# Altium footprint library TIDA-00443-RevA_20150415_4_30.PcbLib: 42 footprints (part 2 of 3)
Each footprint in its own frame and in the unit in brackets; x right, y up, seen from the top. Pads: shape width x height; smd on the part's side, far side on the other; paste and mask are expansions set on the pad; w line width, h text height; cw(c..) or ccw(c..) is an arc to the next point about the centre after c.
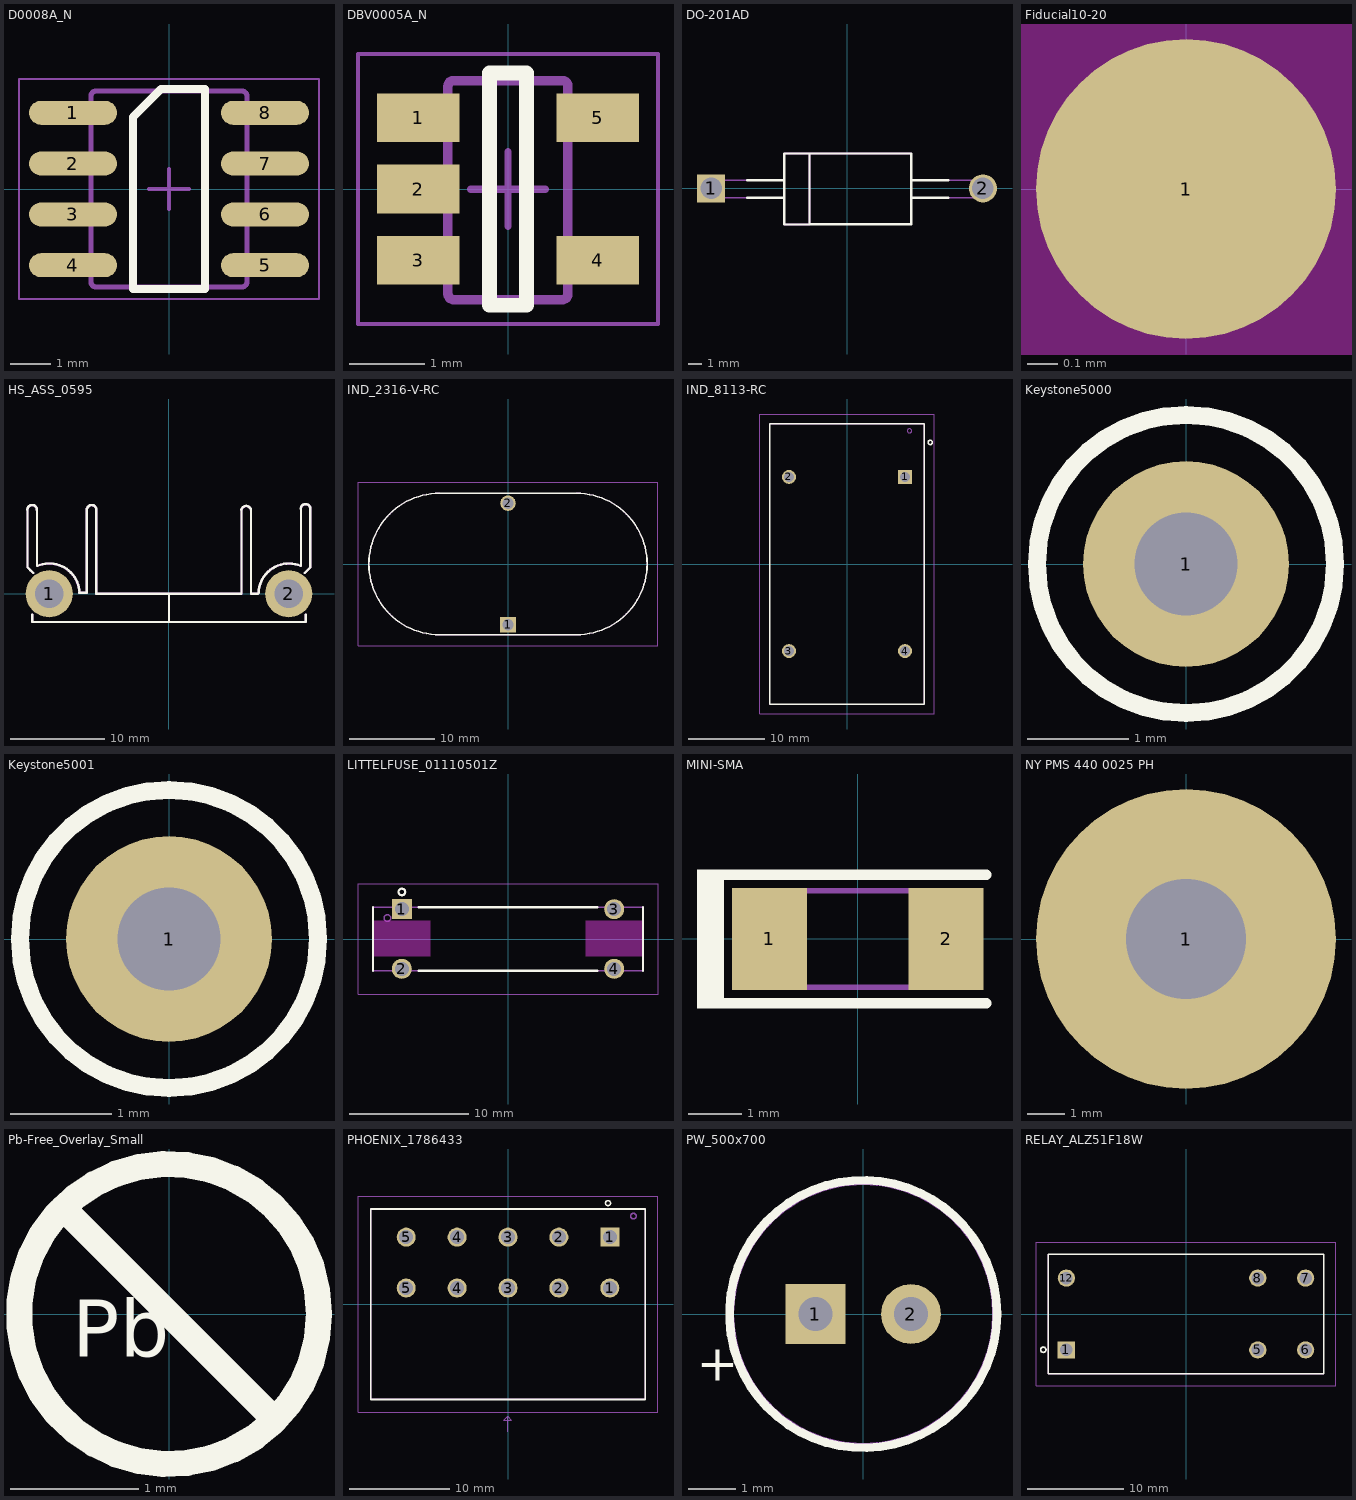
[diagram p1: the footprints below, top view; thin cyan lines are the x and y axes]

## D0008A_N [mm] "SOIC, 8-Leads, Body 4.9x3.9mm, Pitch 1.27mm, IPC Medium Density"
height 1.75
pads (8):
  oval 2.2x0.6 smd: 1(-2.4,1.905) 2(-2.4,0.635) 3(-2.4,-0.635) 4(-2.4,-1.905) 5(2.4,-1.905) 6(2.4,-0.635) 7(2.4,0.635) 8(2.4,1.905)
Top Overlay:
  lines w0.2: -0.9,-2.5 -0.9,1.8 -0.2,2.5 0.9,2.5 0.9,-2.5 -0.9,-2.5
Mechanical 5:
  lines w0.127: -2.375,-2.095 -1.995,-2.095 -1.952,-2.095 -1.952,-1.715 -1.995,-1.715 -2.375,-1.715 ; -2.375,-2.095 -2.589,-2.095 -3.002,-2.095 -3.002,-1.715 -2.589,-1.715 -2.375,-1.715 ; -2.375,-2.095 -2.375,-1.715 ; -2.375,-0.825 -1.995,-0.825 -1.952,-0.825 -1.952,-0.445 -1.995,-0.445 -2.375,-0.445 ; -2.375,-0.825 -2.589,-0.825 -3.002,-0.825 -3.002,-0.445 -2.589,-0.445 -2.375,-0.445 ; -2.375,-0.825 -2.375,-0.445 ; -2.375,0.445 -1.995,0.445 -1.952,0.445 -1.952,0.825 -1.995,0.825 -2.375,0.825 ; -2.375,0.445 -2.589,0.445 -3.002,0.445 -3.002,0.825 -2.589,0.825 -2.375,0.825 ; -2.375,0.445 -2.375,0.825 ; -2.375,1.715 -1.995,1.715 -1.952,1.715 -1.952,2.095 -1.995,2.095 -2.375,2.095 ; -2.375,1.715 -2.589,1.715 -3.002,1.715 -3.002,2.095 -2.589,2.095 -2.375,2.095 ; -2.375,1.715 -2.375,2.095 ; -0.332,-2.45 -1.825,-2.45 -1.826,-2.45 cw(c-1.825,-2.323) -1.952,-2.324 -1.952,-2.323 -1.952,2.323 -1.952,2.324 cw(c-1.825,2.323) -1.826,2.45 -1.825,2.45 -0.332,2.45 ; -0.332,-2.45 -0.182,-2.45 ; -0.332,-2.45 -0.182,-2.45 ; -0.332,2.45 -0.182,2.45 ; -0.332,2.45 -0.182,2.45 ; -0.182,-2.45 0.178,-2.45 ; -0.182,2.45 0.178,2.45 ; 0.178,-2.45 0.328,-2.45 ; 0.178,-2.45 0.328,-2.45 ; 0.178,2.45 0.328,2.45 ; 0.178,2.45 0.328,2.45 ; 0.328,-2.45 1.821,-2.45 1.822,-2.45 ccw(c1.821,-2.323) 1.948,-2.324 1.948,-2.323 1.948,2.323 1.948,2.324 ccw(c1.821,2.323) 1.822,2.45 1.821,2.45 0.328,2.45 ; 2.371,-2.095 2.585,-2.095 2.998,-2.095 2.998,-1.715 2.585,-1.715 2.371,-1.715 ; 2.371,-2.095 1.991,-2.095 1.948,-2.095 1.948,-1.715 1.991,-1.715 2.371,-1.715 ; 2.371,-2.095 2.371,-1.715 ; 2.371,-0.825 2.585,-0.825 2.998,-0.825 2.998,-0.445 2.585,-0.445 2.371,-0.445 ; 2.371,-0.825 1.991,-0.825 1.948,-0.825 1.948,-0.445 1.991,-0.445 2.371,-0.445 ; 2.371,-0.825 2.371,-0.445 ; 2.371,0.445 2.585,0.445 2.998,0.445 2.998,0.825 2.585,0.825 2.371,0.825 ; 2.371,0.445 1.991,0.445 1.948,0.445 1.948,0.825 1.991,0.825 2.371,0.825 ; 2.371,0.445 2.371,0.825 ; 2.371,1.715 2.585,1.715 2.998,1.715 2.998,2.095 2.585,2.095 2.371,2.095 ; 2.371,1.715 1.991,1.715 1.948,1.715 1.948,2.095 1.991,2.095 2.371,2.095 ; 2.371,1.715 2.371,2.095
  text ".Designator" at 0.698,0.241 h0.76
Mechanical 15:
  lines w0.05: -3.75,-2.75 -3.75,2.75 3.75,2.75 3.75,-2.75 -3.75,-2.75
  lines w0.1: -0.5,0 0.5,0 ; 0,-0.5 0,0.5
3D body: height 1.63, standoff 0, extent -3,-2.45 3,2.45

## DBV0005A_N [mm] "SOT23, 5-Leads, Body 2.9x1.6mm, Pitch 0.95mm, Lead Span 2.8mm, IPC Medium Density"
height 1.45
pads (5):
  rect 1.1x0.65 smd: 1(-1.2,0.95) 2(-1.2,0) 3(-1.2,-0.95) 4(1.2,-0.95) 5(1.2,0.95)
Top Overlay:
  lines w0.2: -0.25,-1.55 0.25,-1.55 0.25,1.55 -0.25,1.55 -0.25,-1.55
Mechanical 5:
  lines w0.127: -0.801,1.371 cw(c-0.725,1.37) -0.725,1.446 ; -0.801,1.37 -0.801,-1.399 -0.801,-1.4 ccw(c-0.725,-1.399) -0.725,-1.475 ; -0.801,1.37 -0.801,1.371 ; -0.725,-1.475 -0.725,-1.475 ; -0.725,-1.475 0.723,-1.475 0.724,-1.475 ccw(c0.723,-1.399) 0.799,-1.4 0.799,-1.399 0.799,1.37 ; -0.725,1.446 0.723,1.446 0.724,1.446 cw(c0.723,1.37) 0.799,1.371 ; -0.725,1.446 -0.725,1.446 ; 0.799,1.37 0.799,1.371 ; -1.423,-1.167 -1.199,-1.167 -1.105,-1.167 -1.088,-1.167 -0.835,-1.167 -0.801,-1.167 -0.801,-0.767 -0.835,-0.767 -1.088,-0.767 -1.105,-0.767 -1.199,-0.767 -1.423,-0.767 -1.423,-1.167 ; -1.423,-0.215 -1.199,-0.215 -1.105,-0.215 -1.088,-0.215 -0.835,-0.215 -0.801,-0.215 -0.801,0.186 -0.835,0.186 -1.088,0.186 -1.105,0.186 -1.199,0.186 -1.423,0.186 -1.423,-0.215 ; -1.423,0.738 -1.199,0.738 -1.105,0.738 -1.088,0.738 -0.835,0.738 -0.801,0.738 -0.801,1.138 -0.835,1.138 -1.088,1.138 -1.105,1.138 -1.199,1.138 -1.423,1.138 -1.423,0.738 ; 0.799,-1.167 0.799,-0.767 0.834,-0.767 1.087,-0.767 1.103,-0.767 1.198,-0.767 1.422,-0.767 1.422,-1.167 1.198,-1.167 1.103,-1.167 1.087,-1.167 0.834,-1.167 0.799,-1.167 ; 0.799,0.738 0.799,1.138 0.834,1.138 1.087,1.138 1.103,1.138 1.198,1.138 1.422,1.138 1.422,0.738 1.198,0.738 1.103,0.738 1.087,0.738 0.834,0.738 0.799,0.738
  text ".Designator" at 0.349,-0.645 h0.76
Mechanical 15:
  lines w0.05: -2,-1.8 -2,1.8 2,1.8 2,-1.8 -2,-1.8
  lines w0.1: -0.5,0 0.5,0 ; 0,-0.5 0,0.5
3D body: height 1.08, standoff -0.01, extent -1.422,-1.461 1.422,1.46

## DO-201AD [mm] "Vishay dimensions"
height 5.5
pads (2):
  rect 2.1x2.1 hole 1.6: 1(-10.16,0)
  round 2.1 hole 1.6: 2(10.16,0)
Top Overlay:
  lines w0.178: -7.47,-0.7 -4.7,-0.7 ; -7.47,0.62 -4.7,0.62 ; -2.8,-2.69 4.8,-2.69 4.8,2.61 -2.8,2.61 ; 4.8,-0.7 7.57,-0.7 ; 4.8,0.62 7.57,0.62 ; -2.8,2.61 -2.8,-2.7 -4.7,-2.7 -4.7,2.61 -2.8,2.61
Mechanical 5:
  lines w0.127: -4.7,-0.7 -7.47,-0.7 -10.11,-0.7 cw(c-10.11,-0.04) -10.11,0.62 -7.47,0.62 -4.7,0.62 ; -2.8,-2.69 4.8,-2.69 4.8,2.61 -2.8,2.61 ; 4.8,-0.7 7.57,-0.7 10.21,-0.7 ccw(c10.21,-0.04) 10.21,0.62 7.57,0.62 4.8,0.62 ; -2.8,2.61 -4.7,2.61 -4.7,-2.7 -2.8,-2.7 -2.8,2.61
  text ".Designator" at 0.787,0.203 h0.76
3D body: height 5.33, standoff -2.54, extent -10.819,-2.741 10.819,2.609

## Fiducial10-20 [mm]
pads (1):
  round 1 smd mask+0.5: 1(0,0)
Top Layer keep-out:
  circle w1.178: c0,0 r0.5

## HS_ASS_0595 [mm]
height 50
pads (2):
  round 5 hole 3: 1(-12.7,0) 2(12.7,0)
Top Overlay:
  lines w0.25: -15,9 -15,2.8 -14.697,2.497 -14.4,2.2 ; -14.5,-2.2 -14.5,-3 14.5,-3 14.5,-2.2 ; -14,3 -14,9 ; -9.5,0.1 -8.7,0.1 -8.7,9 ; -7.7,9 -7.7,0 0,0 ; 0,-3 0,0 ; 7.7,9 7.7,0 0,0 ; 8.7,9 8.7,0 9.413,0 ; 14,3 14,9 ; 14.4,2.2 14.712,2.512 15,2.8 15,2.9 15,9
  lines w0.254: -15.02,8.9 cw(c-14.51,8.9) -14,8.9 ; -13.974,2.942 cw(c-12.687,0.01) -9.487,0.1 ; -8.7,8.9 cw(c-8.19,8.9) -7.68,8.9 ; 7.68,8.9 cw(c8.19,8.79) 8.7,8.9 ; 9.512,0.1 cw(c12.713,0.01) 13.979,2.951 ; 13.98,9 cw(c14.49,9) 15,9
Mechanical 5:
  lines w0.25: -15,8.9 -15,2.8 -14.4,2.2 ; -14.5,-2.2 -14.5,-3 14.5,-3 14.5,-2.2 ; -14,3.1 -14,8.9 ; -8.7,9 -8.7,0.1 ; -7.7,8.9 -7.7,0 7.7,0 7.7,8.9 ; 0,-3 0,0 ; 8.7,8.9 8.7,0 9.4,0 ; 14,3 14,9 ; 14.4,2.2 15,2.8 ; 15,9 15,2.8 ; -14.4,2.2 -14.4,2.2 ; -8.7,0.1 -9.5,0.1 -8.7,0.1 ; 15,2.8 15,2.8
  lines w0.254: -15,8.9 cw(c-14.5,8.9) -14,8.9 ; -13.938,2.952 cw(c-12.7,0) -9.5,0.1 ; -8.7,8.9 cw(c-8.2,8.9) -7.7,8.9 ; 7.7,8.8 cw(c8.2,8.8) 8.7,8.8 ; 9.5,0.1 cw(c12.7,0) 13.973,2.938 ; 14,9 cw(c14.5,9) 15,9
  text ".Designator" at 1.016,0.787 h0.76
3D body: height 50, standoff 0, extent -15.1,-3.1 15.1,9.5
3D body: height 4.5, standoff 0, extent 10.22,-2.495 15.2,2.495
3D body: height 4.5, standoff 0, extent -15.18,-2.495 -10.2,2.495

## IND_2316-V-RC [mm] "INDUCTOR, TOROID, VERTICAL, 2PIN, TH"
height 32.512
pads (2):
  rect 1.82x1.82 / inner round 1.82 / far side rect 1.82x1.82 hole 1.32: 1(0,-7.112)
  round 1.82 hole 1.32: 2(0,7.112)
Top Overlay:
  lines w0.178: -8.001,-8.255 cw(c-8.001,0) -8.001,8.255 8.001,8.255 cw(c8.001,0) 8.001,-8.255 -8.001,-8.255
Bottom Overlay:
  lines w0.178: -15.775,-2.777 cw(c-8.001,0) -15.588,3.252 ; -13.59,6.076 cw(c-8.001,0) -8.001,8.255 ; -13.553,-6.109 ccw(c-8.001,0) -8.001,-8.255 ; -5.501,8.255 -2,8.255 ; -5.25,-8.255 -1.749,-8.255 ; 1.749,8.255 5.25,8.255 ; 2,-8.255 5.501,-8.255 ; 7.68,8.249 cw(c8.001,0) 14.473,5.124 ; 8.001,-8.255 ccw(c8.001,0) 14.986,-4.399 ; 15.575,3.283 cw(c8.001,0) 15.948,-2.235
Mechanical 5:
  lines w0.127: -8.001,-8.255 cw(c-8.001,0) -8.001,8.255 8.001,8.255 cw(c8.001,0) 8.001,-8.255 -8.001,-8.255
  text ".Designator" at -1.524,-0.508 h0.76
Mechanical 15:
  lines w0.05: -17.526,-9.525 -17.526,9.525 17.526,9.525 17.526,-9.525 -17.526,-9.525
3D body: height 32.51, standoff 0, extent -16.256,-8.255 16.256,8.255

## IND_8113-RC [mm] "INDUCTOR, CHOKE, COMMON MODE, 4 PIN, TH"
height 38.1
pads (4):
  rect 1.85x1.85 / inner round 1.85 / far side rect 1.85x1.85 hole 1.35 paste+0 mask+0.05: 1(7.62,11.43)
  round 1.85 hole 1.35 paste+0 mask+0.05: 2(-7.62,11.43) 3(-7.62,-11.43) 4(7.62,-11.43)
Top Overlay:
  circle w0.178: c10.922,15.951 r0.279
  lines w0.178: -10.16,-18.415 -10.16,18.415 10.16,18.415 10.16,-18.415 -10.16,-18.415
Bottom Overlay:
  lines w0.178: -10.16,-15.5 -10.16,-11 ; -10.16,-8.5 -10.16,-4.5 ; -10.16,-1.25 -10.16,3 ; -10.16,5.5 -10.16,10 ; -10.16,12.5 -10.16,16.5 ; -8.75,-18.415 -4.5,-18.415 ; -8.75,18.415 -4.5,18.415 ; -2,-18.415 2.5,-18.415 ; -2,18.415 2.5,18.415 ; 5,-18.415 9,-18.415 ; 5,18.415 9,18.415 ; 10.16,-15.25 10.16,-10.75 ; 10.16,-8.25 10.16,-4.25 ; 10.16,-1 10.16,3.25 ; 10.16,5.75 10.16,10.25 ; 10.16,12.75 10.16,16.75
Mechanical 5:
  circle w0.127: c8.204,17.475 r0.279
  lines w0.127: -10.16,-18.415 10.16,-18.415 10.16,18.415 -10.16,18.415 -10.16,-18.415
  text ".Designator" at 1.27,0.406 h0.76
Mechanical 15:
  lines w0.05: -11.43,-19.685 -11.43,19.685 11.43,19.685 11.43,-19.685 -11.43,-19.685
Mechanical 17:
  text "LEAD LENGTH: 5.08 MM" at -9.5,14.75 h1
3D body: height 38.1, standoff 0, extent -10.16,-18.415 10.16,18.415

## Keystone5000 [mil] "For Keystone 500x miniature loop terminals"
height 181.1
pads (1):
  round 80 hole 40: 1(0,0)
Top Overlay:
  circle w7: c0,0 r58
Mechanical 5:
  circle w5: c0,0 r58.31
  text ".Designator" at -42,-17 h30
3D body: height 181.97, standoff -118.11, extent -49,-49 49.04,49.24

## Keystone5001 [mil] "For Keystone 500x miniature loop terminals"
height 181.1
pads (1):
  round 80 hole 40: 1(0,0)
Top Overlay:
  circle w7: c0,0 r58
Mechanical 5:
  circle w5: c0,0 r58.31
  text ".Designator" at -40,-13 h30
3D body: height 181.97, standoff -118.11, extent -49,-49 49.04,49.24

## LITTELFUSE_01110501Z [mm] "FUSE CLIP, CARTRIDGE, 250V, 10A, PCB"
height 7.1
pads (4):
  rect 1.67x1.67 / inner round 1.67 / far side rect 1.67x1.67 hole 1.17: 1(-8.9,2.5)
  round 1.67 hole 1.17: 2(-8.9,-2.5) 3(8.9,2.5) 4(8.9,-2.5)
Top Layer keep-out:
  rectangle: -11.292,-1.468 -6.492,1.532
  rectangle: 6.508,-1.468 11.308,1.532
Top Overlay:
  circle w0.178: c-8.892,3.942 r0.279
  lines w0.178: -11.3,-2.66 -11.3,2.66 ; -7.5,-2.66 7.5,-2.66 ; -7.5,2.66 7.5,2.66 ; 11.3,-2.66 11.3,2.66
Bottom Overlay:
  lines w0.178: -11.3,-2.66 -11.3,-0.985 ; -11.3,0.985 -11.3,2.66 ; -7.5,-2.66 -5.825,-2.66 ; -7.5,2.66 -5.825,2.66 ; -4.15,-2.66 -2.475,-2.66 ; -4.15,2.66 -2.475,2.66 ; -0.8,-2.66 0.875,-2.66 ; -0.8,2.66 0.875,2.66 ; 2.55,-2.66 4.225,-2.66 ; 2.55,2.66 4.225,2.66 ; 5.825,2.66 7.5,2.66 ; 5.9,-2.66 7.575,-2.66 ; 11.3,-2.66 11.3,-0.985 ; 11.3,0.985 11.3,2.66
Mechanical 5:
  circle w0.127: c-10.109,1.753 r0.279
  lines w0.127: -11.3,-2.66 -11.3,2.66 11.3,2.66 11.3,-2.66 -11.3,-2.66
  text ".Designator" at -1.88,0.61 h0.76
Mechanical 15:
  lines w0.05: -12.57,-4.63 12.57,-4.63 12.57,4.63 -12.57,4.63 -12.57,-4.63
3D body: height 7.1, standoff 0, extent -11.3,-2.66 11.3,2.66

## MINI-SMA [mm] "COMCHIP"
height 1.45
pads (2):
  rect 1.4x1.9 smd: 1(-1.65,0) 2(1.65,0)
Top Overlay:
  rectangle: -2.999,-1.3 -2.499,1.3
  lines w0.2: -2.8,-1.2 2.4,-1.2 ; -2.8,1.2 2.4,1.2
Mechanical 5:
  rectangle: -2,-0.9 -1.3,0.9
  lines w0.1: -2,-0.9 -1.5,-0.9 0,-0.9 2,-0.9 2,0.9 -2,0.9 -2,-0.9
  text ".Designator" at -0.356,-0.279 h0.76
3D body: height 1.7, standoff 0, extent -1.95,-0.9 1.95,0.9

## NY PMS 440 0025 PH [mm] "4-40 nylon screw and mounting hole"
height 1.905
pads (1):
  round 8 hole 3.2: 1(0,0)
Mechanical 5:
  circle w0.127: c0,0 r3.789
  text ".Designator" at -1.524,-0.508 h1.02
3D body: height 2.69, standoff -8.74, extent -3.302,-3.3 3.296,3.3

## Pb-Free_Overlay_Small [mm]
Top Overlay:
  circle w0.203: c0,0 r1.168
  lines w0.203: -0.826,0.826 0.826,-0.826
  text "Pb" at -0.752,-0.48 h0.76

## PHOENIX_1786433 [mm] "TERM BLOCK, HDR, 5POS, R/A 5.08MM"
height 10.2
pads (10):
  round 1.9 hole 1.4: 1(10.16,1.61) 2(5.08,1.61) 2(5.08,6.69) 3(0,1.61) 3(0,6.69) 4(-5.08,1.61) 4(-5.08,6.69) 5(-10.16,1.61) 5(-10.16,6.69)
  rect 1.9x1.9 / inner round 1.9 / far side rect 1.9x1.9 hole 1.4: 1(10.16,6.69)
Top Overlay:
  circle w0.152: c9.982,10.084 r0.254
  lines w0.178: -13.7,-9.5 13.7,-9.5 13.7,9.5 -13.7,9.5 -13.7,-9.5
  text ".Designator" at 14.097,3.658 h0.76
Bottom Overlay:
  lines w0.178: -13.7,-9.5 -13.7,-8.475 ; -13.7,-7.1 -13.7,-5.5 ; -13.7,-4.1 -13.7,-2.5 ; -13.7,-1.1 -13.7,0.5 ; -13.7,1.9 -13.7,3.5 ; -13.7,4.9 -13.7,6.5 ; -13.7,7.9 -13.7,9.5 ; -11.913,9.5 -10.338,9.5 ; -10.846,-9.499 -9.271,-9.499 ; -8.913,9.5 -7.338,9.5 ; -7.846,-9.509 -6.271,-9.509 ; -5.913,9.5 -4.338,9.5 ; -4.846,-9.5 -3,-9.5 ; -2.413,9.5 -0.838,9.5 ; -1.168,-9.5 0.406,-9.5 ; 0.587,9.491 2.162,9.491 ; 1.832,-9.5 3.406,-9.5 ; 3.587,9.491 5.162,9.491 ; 4.832,-9.5 6.406,-9.5 ; 6.587,9.491 8.162,9.491 ; 7.832,-9.5 9.406,-9.5 ; 9.587,9.491 11.162,9.491 ; 10.832,-9.5 12.406,-9.5 ; 13.7,-9.5 13.7,-7.9 ; 13.701,-6.525 13.701,-4.925 ; 13.701,-3.525 13.701,-1.925 ; 13.701,-0.525 13.701,1.075 ; 13.701,2.475 13.701,4.075 ; 13.701,5.475 13.701,7.075 ; 13.701,8.475 13.701,9.5
Mechanical 5:
  circle w0.127: c12.522,8.788 r0.279
  lines w0.127: -13.7,-9.5 -13.7,9.5 13.7,9.5 13.7,-9.5 -13.7,-9.5
  text ".Designator" at -0.559,3.835 h0.76
Mechanical 15:
  lines w0.05: -14.97,-10.77 14.97,-10.77 14.97,10.77 -14.97,10.77 -14.97,-10.77
Mechanical 16:
  lines w0.05: -0.044,-12.732 -0.044,-11.208 ; -0.044,-11.208 0.337,-11.589 -0.425,-11.589 -0.044,-11.208
Mechanical 17:
  text "LEAD LENGTH: 3.50MM" at -9.487,-4.244 h1
  text "MATING SIDE" at -5.512,-14.138 h1
3D body: height 10.2, standoff 0, extent -13.716,-9.515 13.716,9.535

## PW_500x700 [mm] "Nichicon"
height 8
pads (2):
  rect 1.25x1.25 hole 0.711: 1(-1,0)
  round 1.25 hole 0.711: 2(1,0)
Top Overlay:
  circle w0.18: c0,0 r2.802
  text "+" at -3.48,-1.397 h0.76
Mechanical 5:
  circle w0.1: c0,0 r2.75
  text ".Designator" at 0.305,-0.813 h0.76
  text "+" at -3.581,-1.473 h0.76
3D body: height 8.01, standoff -4, extent -2.728,-2.745 2.75,2.746

## RELAY_ALZ51F18W [mm] "RELAY, SPST-NO(1 Form A), 16A, 18V, TH"
height 15.7
pads (6):
  rect 1.8x1.8 / inner round 1.8 / far side rect 1.8x1.8 hole 1.3: 1(-12.5,-3.75)
  round 1.8 hole 1.3: 5(7.5,-3.75) 6(12.5,-3.75) 7(12.5,3.75) 8(7.5,3.75) 12(-12.5,3.75)
Top Overlay:
  circle w0.178: c-14.91,-3.734 r0.279
  lines w0.178: -14.4,-6.25 14.4,-6.25 14.4,6.25 -14.4,6.25 -14.4,-6.25
Mechanical 5:
  lines w0.127: -14.4,-6.25 -14.4,6.25 14.4,6.25 14.4,-6.25 -14.4,-6.25
  text ".Designator" at 0.965,0.584 h0.76
Mechanical 15:
  lines w0.05: -15.67,-7.52 15.67,-7.52 15.67,7.52 -15.67,7.52 -15.67,-7.52
3D body: height 15.7, standoff 0, extent -14.4,-6.25 14.4,6.25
